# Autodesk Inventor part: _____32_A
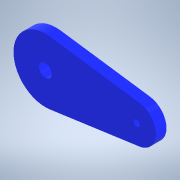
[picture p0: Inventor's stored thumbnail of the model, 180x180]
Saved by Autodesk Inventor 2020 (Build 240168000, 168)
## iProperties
Created: 2017-09
Part Number: _____32_A
Material: Générique
Document SubType Name: Modeling
Designer: bruno
Density: 1 g/cm^3
Appearance: Bleu - Peinture murale - Brillant
Mass: 7.40966 g
Surface Area: 40.5751 cm^2
Volume: 7.40966 cm^3
Sending System: SolidWorks 2016
Author: bruno
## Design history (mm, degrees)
feature "Importée1"
node "Solide1"
